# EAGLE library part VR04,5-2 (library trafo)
TRANSFORMER 1 primary winding, 2 secondary windings, mounting holes BLOCK
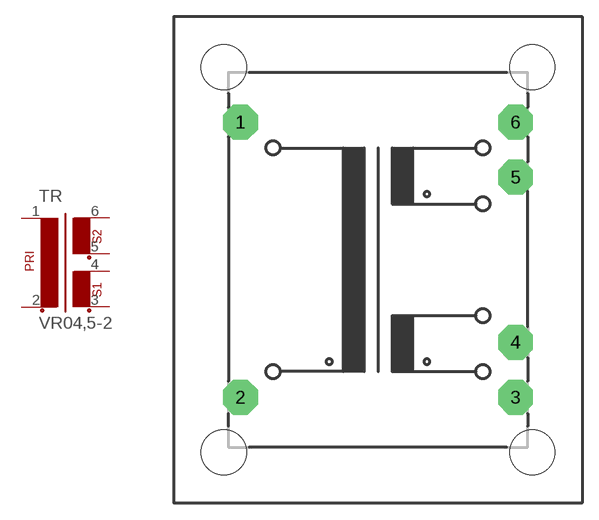
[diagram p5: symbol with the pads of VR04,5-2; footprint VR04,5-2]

Designator prefix TR

## VR04,5-2  [VR04,5-2]
1  1  pas
2  2  pas
3  3  pas
4  4  pas
5  5  pas
6  6  pas

## Footprint VR04,5-2 (pad centres in mm)
TRANSFORMER 1 primary winding, 2 secondary windings, mounting holes
drill 1.397 pad 3.175 octagon: 1 -12.497,12.497; 2 -12.497,-12.497; 3 12.497,-12.497; 4 12.497,-7.493; 5 12.497,7.493; 6 12.497,12.497
hole 4.115 at -14.021,-17.501
hole 4.115 at -14.021,17.501
hole 4.115 at 14.021,17.501
hole 4.115 at 14.021,-17.501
